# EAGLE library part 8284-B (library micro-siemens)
MICROPROCESSOR/PERIPHERAL DEVICE
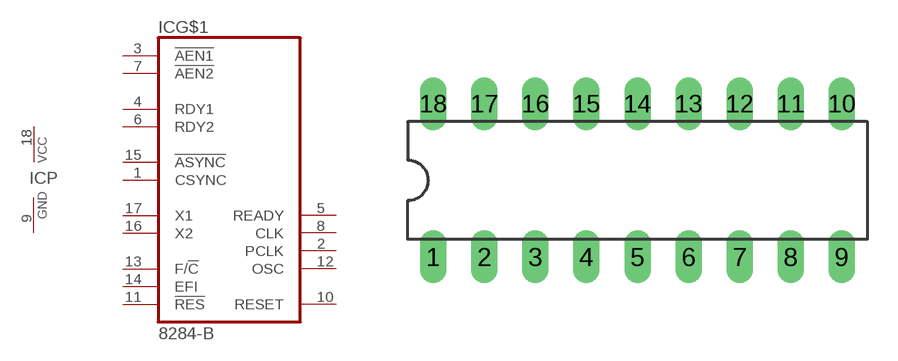
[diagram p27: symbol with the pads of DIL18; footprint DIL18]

Designator prefix IC; gates G$1=8284-B P=VCCGND

## 8284-B (OC_FARNELL: unknown; OC_NEWARK: unknown)  [DIL18]
1  G$1:CSYNC  in
2  G$1:PCLK  out
3  G$1:!AEN1  in
4  G$1:RDY1  in
5  G$1:READY  out
6  G$1:RDY2  in
7  G$1:!AEN2  in
8  G$1:CLK  out
9  P:GND  pwr
10  G$1:RESET  out
11  G$1:!RES  in
12  G$1:OSC  out
13  G$1:F/!C  in
14  G$1:EFI  in
15  G$1:!ASYNC  in
16  G$1:X2  in
17  G$1:X1  in
18  P:VCC  pwr

## Footprint DIL18 (pad centres in mm)
Dual In Line Package
drill 0.813 long: 1 -10.16,-3.81; 2 -7.62,-3.81; 3 -5.08,-3.81; 4 -2.54,-3.81; 5 0,-3.81; 6 2.54,-3.81; 7 5.08,-3.81; 8 7.62,-3.81; 9 10.16,-3.81; 10 10.16,3.81; 11 7.62,3.81; 12 5.08,3.81; 13 2.54,3.81; 14 0,3.81; 15 -2.54,3.81; 16 -5.08,3.81; 17 -7.62,3.81; 18 -10.16,3.81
